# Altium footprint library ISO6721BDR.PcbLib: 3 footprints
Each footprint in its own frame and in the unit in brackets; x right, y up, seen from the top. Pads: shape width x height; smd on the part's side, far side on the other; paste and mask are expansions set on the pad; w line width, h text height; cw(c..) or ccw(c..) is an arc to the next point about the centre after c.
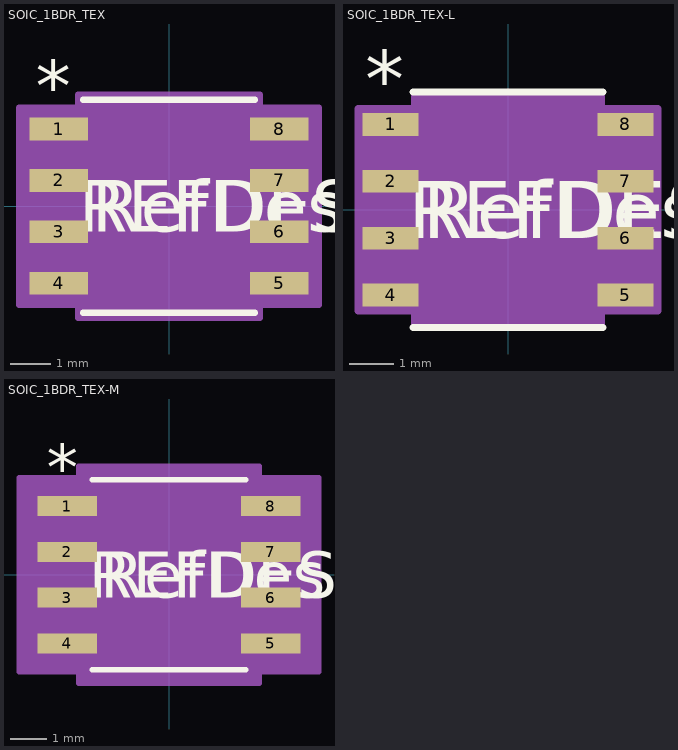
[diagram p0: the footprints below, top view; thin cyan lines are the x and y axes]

## SOIC_1BDR_TEX [mil]
pads (8):
  rect 57.28x21.97 smd paste+0 mask+0: 1(-107.14,75) 2(-107.14,25) 3(-107.14,-25) 4(-107.14,-75) 5(107.14,-75) 6(107.14,-25) 7(107.14,25) 8(107.14,75)
Top Overlay:
  lines w6: -83.5,-103.5 83.5,-103.5 ; -83.5,103.5 83.5,103.5
  text "REFDES" at -87.5,-25 h50
  text "*" at -129.64,91.97 h50
  text "RefDes" at -75,-25 h50
Mechanical 13:
  lines w0: -12,98.5 ccw(c0,98.5) 12,98.5
  lines w1: -122,-85 -122,-65 -78.5,-65 -78.5,-85 -122,-85 ; -122,-35 -122,-15 -78.5,-15 -78.5,-35 -122,-35 ; -122,15 -122,35 -78.5,35 -78.5,15 -122,15 ; -122,65 -122,85 -78.5,85 -78.5,65 -122,65 ; -78.5,-98.5 78.5,-98.5 78.5,98.5 -78.5,98.5 -78.5,-98.5 ; 78.5,-85 78.5,-65 122,-65 122,-85 78.5,-85 ; 78.5,-35 78.5,-15 122,-15 122,-35 78.5,-35 ; 78.5,15 78.5,35 122,35 122,15 78.5,15 ; 78.5,65 78.5,85 122,85 122,65 78.5,65
  text "*" at -76,45.5 h50
  text "RefDes2" at -87.5,-25 h50
Mechanical 15:
  region: -88.5,-95.98 -145.78,-95.98 -145.78,95.98 -88.5,95.98 -88.5,108.5 88.5,108.5 88.5,95.98 145.78,95.98 145.78,-95.98 88.5,-95.98 88.5,-108.5 -88.5,-108.5
  lines w6: -145.78,-95.98 -145.78,95.98 -88.5,95.98 -88.5,108.5 88.5,108.5 88.5,95.98 145.78,95.98 145.78,-95.98 88.5,-95.98 88.5,-108.5 -88.5,-108.5 -88.5,-95.98 -145.78,-95.98
3D body "SOIC_1BDR_TEX.step": height 69.09, standoff 0, extent -122.01,-98.5 122.01,98.5

## SOIC_1BDR_TEX-L [mil]
pads (8):
  rect 49.41x20 smd paste+0 mask+0: 1(-103.2,75) 2(-103.2,25) 3(-103.2,-25) 4(-103.2,-75) 5(103.2,-75) 6(103.2,-25) 7(103.2,25) 8(103.2,75)
Top Overlay:
  lines w6: -83.5,-103.5 83.5,-103.5 ; -83.5,103.5 83.5,103.5
  text "REFDES" at -87.5,-25 h50
  text "*" at -125.7,90 h50
  text "RefDes" at -75,-25 h50
Mechanical 13:
  lines w0: -12,98.5 ccw(c0,98.5) 12,98.5
  lines w1: -122,-85 -122,-65 -78.5,-65 -78.5,-85 -122,-85 ; -122,-35 -122,-15 -78.5,-15 -78.5,-35 -122,-35 ; -122,15 -122,35 -78.5,35 -78.5,15 -122,15 ; -122,65 -122,85 -78.5,85 -78.5,65 -122,65 ; -78.5,-98.5 78.5,-98.5 78.5,98.5 -78.5,98.5 -78.5,-98.5 ; 78.5,-85 78.5,-65 122,-65 122,-85 78.5,-85 ; 78.5,-35 78.5,-15 122,-15 122,-35 78.5,-35 ; 78.5,15 78.5,35 122,35 122,15 78.5,15 ; 78.5,65 78.5,85 122,85 122,65 78.5,65
  text "*" at -76,45.5 h50
  text "RefDes2" at -87.5,-25 h50
Mechanical 15:
  region: -82.5,-89 -131.91,-89 -131.91,89 -82.5,89 -82.5,102.5 82.5,102.5 82.5,89 131.91,89 131.91,-89 82.5,-89 82.5,-102.5 -82.5,-102.5
  lines w6: -131.91,-89 -131.91,89 -82.5,89 -82.5,102.5 82.5,102.5 82.5,89 131.91,89 131.91,-89 82.5,-89 82.5,-102.5 -82.5,-102.5 -82.5,-89 -131.91,-89
3D body "SOIC_1BDR_TEX.step": height 69.09, standoff 0, extent -122.01,-98.5 122.01,98.5

## SOIC_1BDR_TEX-M [mil]
pads (8):
  rect 65.15x21.97 smd paste+0 mask+0: 1(-111.08,75) 2(-111.08,25) 3(-111.08,-25) 4(-111.08,-75) 5(111.08,-75) 6(111.08,-25) 7(111.08,25) 8(111.08,75)
Top Overlay:
  lines w6: -83.5,-103.5 83.5,-103.5 ; -83.5,103.5 83.5,103.5
  text "REFDES" at -87.5,-25 h50
  text "*" at -133.58,91.97 h50
  text "RefDes" at -75,-25 h50
Mechanical 13:
  lines w0: -12,98.5 ccw(c0,98.5) 12,98.5
  lines w1: -122,-85 -122,-65 -78.5,-65 -78.5,-85 -122,-85 ; -122,-35 -122,-15 -78.5,-15 -78.5,-35 -122,-35 ; -122,15 -122,35 -78.5,35 -78.5,15 -122,15 ; -122,65 -122,85 -78.5,85 -78.5,65 -122,65 ; -78.5,-98.5 78.5,-98.5 78.5,98.5 -78.5,98.5 -78.5,-98.5 ; 78.5,-85 78.5,-65 122,-65 122,-85 78.5,-85 ; 78.5,-35 78.5,-15 122,-15 122,-35 78.5,-35 ; 78.5,15 78.5,35 122,35 122,15 78.5,15 ; 78.5,65 78.5,85 122,85 122,65 78.5,65
  text "*" at -76,45.5 h50
  text "RefDes2" at -87.5,-25 h50
Mechanical 15:
  region: -98.5,-105.98 -163.65,-105.98 -163.65,105.98 -98.5,105.98 -98.5,118.5 98.5,118.5 98.5,105.98 163.65,105.98 163.65,-105.98 98.5,-105.98 98.5,-118.5 -98.5,-118.5
  lines w6: -163.65,-105.98 -163.65,105.98 -98.5,105.98 -98.5,118.5 98.5,118.5 98.5,105.98 163.65,105.98 163.65,-105.98 98.5,-105.98 98.5,-118.5 -98.5,-118.5 -98.5,-105.98 -163.65,-105.98
3D body "SOIC_1BDR_TEX.step": height 69.09, standoff 0, extent -122.01,-98.5 122.01,98.5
